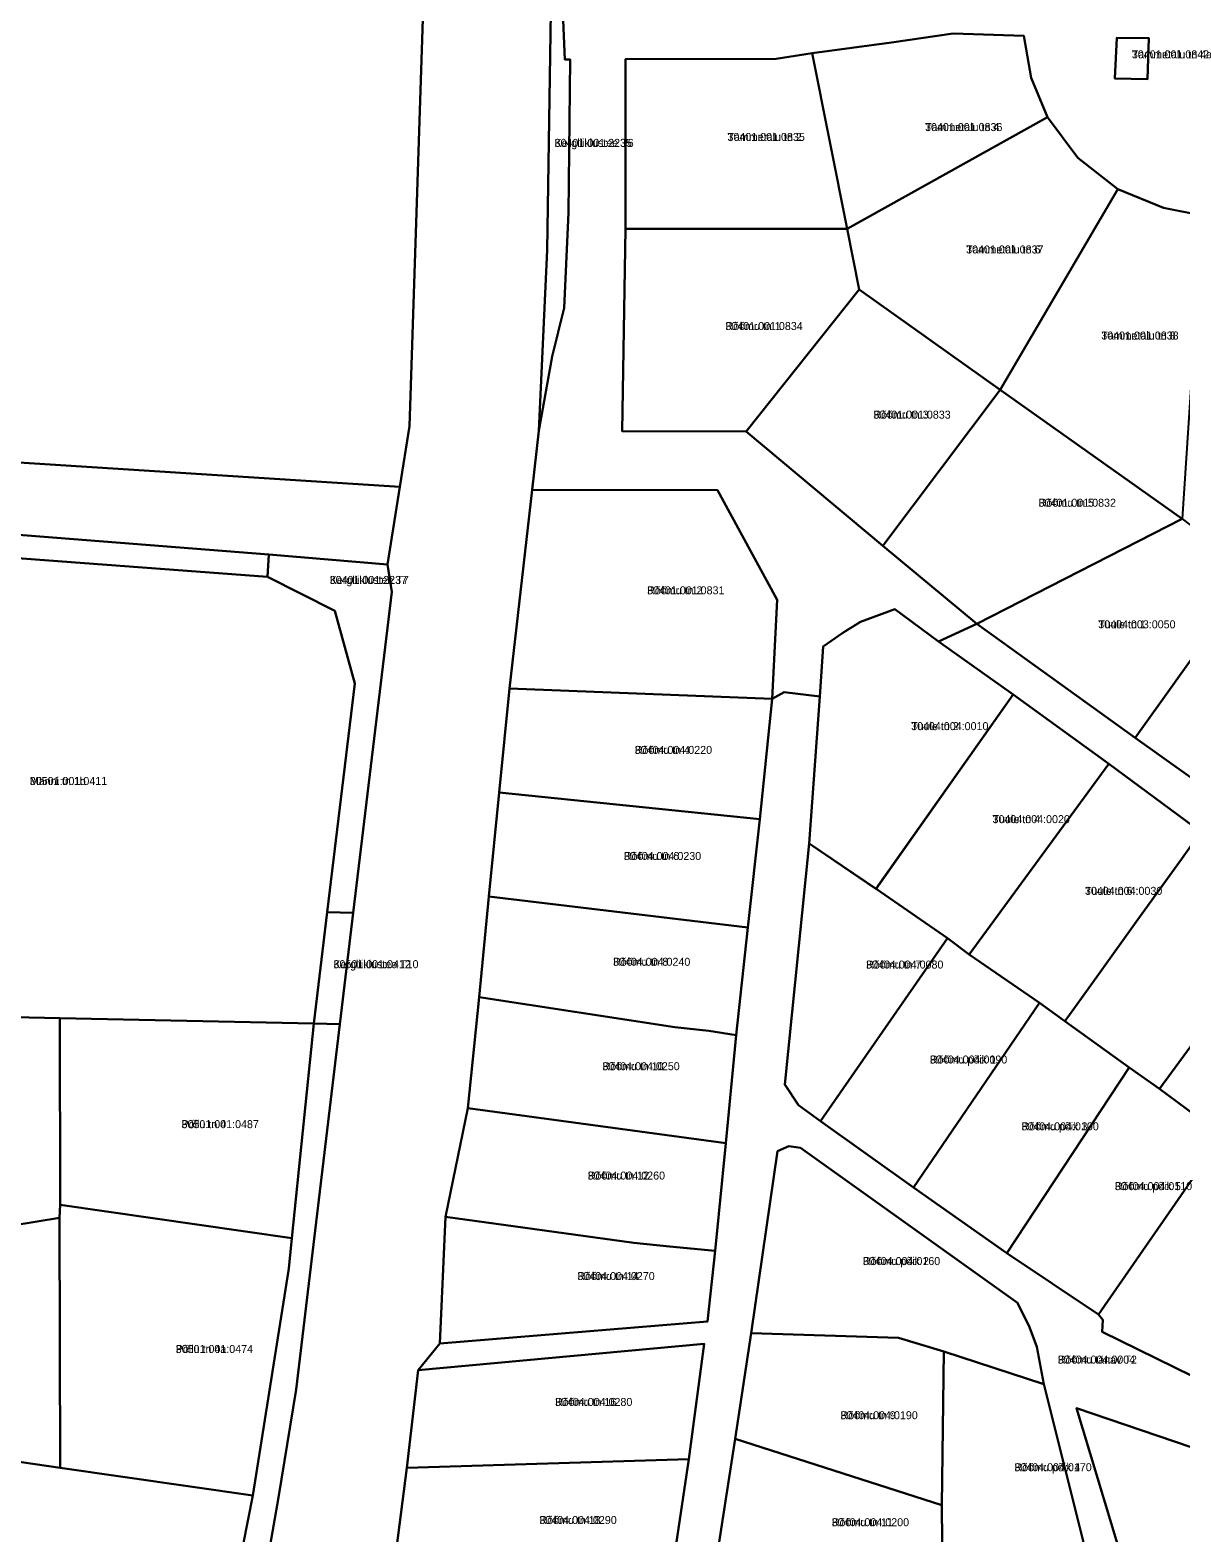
# Model space of a CAD drawing. Extents: x 542681 to 554572, y 6566489 to 6580482.
# Drawn here: x 543956.1 to 544171.9, y 6577252.9 to 6577534.7 of the extents above; entities that cross this region are included whole.
import ezdxf

# ---------------------------------------------------------------- set-up
doc = ezdxf.new("R2010")
doc.units = 0
for name, color, linetype in [('L_AADRESS', 7, 'Continuous'), ('PIIR', 7, 'Continuous'), ('TUNNUS', 7, 'Continuous')]:
    doc.layers.add(name, color=color, linetype=linetype)

msp = doc.modelspace()

# ---------------------------------------------------------------- linework, layer by layer
at = {"layer": 'PIIR'}
for points in [[(544030.15, 6577550.17), (544027.21, 6577460.39), (544025.4, 6577449.01), (543908.86, 6577456.48), (543804.25, 6577490.77), (543783.82, 6577497.46), (543778.02, 6577479.87), (543751.94, 6577490.62), (543735, 6577461.17), (543686.43, 6577482.79), (543669.69, 6577490.19), (543653.77, 6577500.52), (543645.51, 6577505.96), (543637.34, 6577511.56), (543597.54, 6577553.16)], [(543807.92, 6576662.98), (543904.97, 6576885.47), (543907.57, 6576895.31), (543910.99, 6576906.44), (543922.56, 6576941.94), (543936.45, 6576984.61), (543948.61, 6577021.3), (543957.88, 6577054.74), (543966.17, 6577087.14), (543974.03, 6577119.2), (543981.47, 6577151), (543988.44, 6577183.28), (543996.05, 6577221.97), (544002.64, 6577259.57), (544005.96, 6577279.79), (544014.14, 6577348.31), (544016.62, 6577369.15), (544023.92, 6577429.37), (544023.1, 6577434.48), (544025.4, 6577449.01), (544027.21, 6577460.39), (544030.15, 6577550.17)], [(544053.92, 6577550.31), (544053, 6577493.41), (544051.47, 6577459.51), (544050.21, 6577448.48), (544045.96, 6577411.21), (544044.02, 6577391.73), (544042.07, 6577372.25), (544040.3, 6577353.35), (544038.17, 6577332.56), (544033.93, 6577312.2), (544032.9, 6577288.43), (544028.86, 6577283.44), (544026.68, 6577265.1), (544024.78, 6577250.04)], [(544175.84, 6577499.89), (544168.56, 6577501.31), (544160.05, 6577504.83), (544152.54, 6577510.7), (544146.85, 6577518.33), (544143.77, 6577525.72), (544142.4, 6577533.6), (544129.14, 6577534.02), (544117.57, 6577532.36), (544102.69, 6577530.34), (544095.98, 6577529.27), (544067.7, 6577529.24), (544067.69, 6577497.41), (544067.11, 6577459.44), (544090.36, 6577459.43), (544115.96, 6577438), (544133.57, 6577423.36), (544126.41, 6577420.01), (544118.24, 6577426.07), (544111.75, 6577423.71), (544108.45, 6577421.66), (544104.77, 6577419.12), (544104.17, 6577409.74), (544097.43, 6577410.56), (544095.19, 6577409.28), (544096.12, 6577427.83), (544084.94, 6577448.42), (544050.21, 6577448.48), (544051.47, 6577459.51), (544053.95, 6577473.5), (544056.21, 6577482.62), (544057.04, 6577500.43), (544057.35, 6577529.17), (544056.35, 6577529.16), (544055.44, 6577549.92)], [(543908.86, 6577456.48), (544025.4, 6577449.01), (544023.1, 6577434.48), (544000.84, 6577436.33), (543906.97, 6577443.7)], [(544075.94, 6577242.44), (544079.61, 6577266.72), (544082.45, 6577288.34), (544028.86, 6577283.44), (544032.9, 6577288.43), (544083.08, 6577292.53), (544084.54, 6577305.77), (544086.52, 6577325.97), (544088.49, 6577346.24), (544090.62, 6577366.41), (544092.91, 6577386.7), (544095.19, 6577409.28), (544097.43, 6577410.56), (544104.17, 6577409.74), (544102.13, 6577382.17), (544097.57, 6577336.98), (544100.14, 6577333.11), (544104.25, 6577330.14), (544121.74, 6577317.66), (544139.24, 6577305.35), (544156.41, 6577293.87), (544157.23, 6577292.89), (544157.1, 6577290.6), (544174, 6577282.28)], [(543952.91, 6577055.9), (543961.04, 6577087.76), (543969.28, 6577119.84), (543973.68, 6577136.98), (543976.6, 6577151.88), (543983, 6577184.45), (543990.52, 6577222.87), (543997.84, 6577259.95), (544004.56, 6577302.46), (544005.14, 6577308.18), (544009.28, 6577348.44), (544014.14, 6577348.31), (544005.96, 6577279.79), (544002.64, 6577259.57), (543996.05, 6577221.97), (543988.44, 6577183.28), (543981.47, 6577151), (543974.03, 6577119.2), (543966.17, 6577087.14), (543957.88, 6577054.74), (543948.61, 6577021.3)], [(544154.25, 6577248.45), (544146.15, 6577280.82), (544144.86, 6577287.82), (544143.45, 6577291.51), (544141.23, 6577296.05), (544100.5, 6577325.14), (544098.33, 6577325.44), (544096.24, 6577324.51), (544091.27, 6577290.34), (544088.25, 6577270.53), (544083.69, 6577241.1)], [(544202.58, 6577252.78), (544201.13, 6577259.66), (544152.26, 6577276.33), (544162.33, 6577242.91)]]:
    msp.add_lwpolyline(points, dxfattribs=at)
for points in [[(544053.92, 6577550.31), (544055.44, 6577549.92), (544056.35, 6577529.16), (544057.35, 6577529.17), (544057.04, 6577500.43), (544056.21, 6577482.62), (544053.95, 6577473.5), (544051.47, 6577459.51), (544053, 6577493.41)], [(544102.69, 6577530.34), (544117.57, 6577532.36), (544129.14, 6577534.02), (544142.4, 6577533.6), (544143.77, 6577525.72), (544146.85, 6577518.33), (544109.25, 6577497.43)], [(544159.85, 6577533.24), (544165.86, 6577533.15), (544165.61, 6577525.48), (544159.44, 6577525.56)], [(544165.86, 6577533.15), (544159.85, 6577533.24), (544159.44, 6577525.56), (544165.61, 6577525.48)], [(544067.7, 6577529.24), (544095.98, 6577529.27), (544102.69, 6577530.34), (544109.25, 6577497.43), (544067.69, 6577497.41)], [(544109.25, 6577497.43), (544146.85, 6577518.33), (544152.54, 6577510.7), (544160.05, 6577504.83), (544137.99, 6577467.25), (544111.52, 6577486.02)], [(544160.05, 6577504.83), (544168.56, 6577501.31), (544175.84, 6577499.89), (544172.06, 6577443.05), (544137.99, 6577467.25)], [(544067.69, 6577497.41), (544109.25, 6577497.43), (544111.52, 6577486.02), (544090.36, 6577459.43), (544067.11, 6577459.44)], [(544111.52, 6577486.02), (544137.99, 6577467.25), (544115.96, 6577438), (544090.36, 6577459.43)], [(544137.99, 6577467.25), (544172.06, 6577443.05), (544133.57, 6577423.36), (544115.96, 6577438)], [(544050.21, 6577448.48), (544084.94, 6577448.42), (544096.12, 6577427.83), (544095.19, 6577409.28), (544045.96, 6577411.21)], [(543879.74, 6577351.15), (543904.27, 6577442.25), (543906.97, 6577443.7), (544000.84, 6577436.33), (544000.56, 6577432.17), (543924.39, 6577437.83), (543912.68, 6577434.71), (543905.78, 6577424.71), (543886.12, 6577351), (543885.8, 6577343.62), (543892.78, 6577300.8), (543888.2, 6577300.08)], [(544163.25, 6577401.97), (544133.57, 6577423.36), (544172.06, 6577443.05), (544185.38, 6577432.88)], [(543905.78, 6577424.71), (543912.68, 6577434.71), (543924.39, 6577437.83), (544000.56, 6577432.17), (544013.18, 6577425.8), (544016.98, 6577412.17), (544011.76, 6577369.27), (544009.28, 6577348.44), (543961.61, 6577349.42), (543921.15, 6577350.31), (543886.12, 6577351)], [(544000.84, 6577436.33), (544023.1, 6577434.48), (544023.92, 6577429.37), (544016.62, 6577369.15), (544011.76, 6577369.27), (544016.98, 6577412.17), (544013.18, 6577425.8), (544000.56, 6577432.17)], [(544163.25, 6577401.97), (544185.38, 6577432.88), (544196.38, 6577424.9), (544206.32, 6577417.64), (544184.57, 6577386.76)], [(544104.17, 6577409.74), (544104.77, 6577419.12), (544108.45, 6577421.66), (544111.75, 6577423.71), (544118.24, 6577426.07), (544126.41, 6577420.01), (544140.38, 6577410.12), (544114.67, 6577373.68), (544102.13, 6577382.17)], [(544133.57, 6577423.36), (544163.25, 6577401.97), (544184.57, 6577386.76), (544205.61, 6577371.6), (544227.39, 6577355.94), (544248.54, 6577340.99), (544254.71, 6577336.16), (544251.67, 6577330.24), (544251.2, 6577329.49), (544246.47, 6577333.34), (544229.05, 6577346.22), (544210.56, 6577358.48), (544193.75, 6577371.48), (544175.61, 6577384.37), (544158.34, 6577397.13), (544140.43, 6577410.12), (544126.41, 6577420.01)], [(544045.96, 6577411.21), (544095.19, 6577409.28), (544092.91, 6577386.7), (544044.02, 6577391.73)], [(544128.08, 6577364.43), (544114.72, 6577373.69), (544140.43, 6577410.12), (544158.34, 6577397.13), (544132.12, 6577361.35)], [(544150.11, 6577348.83), (544145.33, 6577352.28), (544132.12, 6577361.35), (544158.34, 6577397.13), (544175.61, 6577384.37), (544171.94, 6577379.25), (544163.79, 6577367.89), (544156.39, 6577357.58), (544150.65, 6577349.58)], [(544044.02, 6577391.73), (544092.91, 6577386.7), (544090.62, 6577366.41), (544042.07, 6577372.25)], [(544100.14, 6577333.11), (544097.57, 6577336.98), (544102.13, 6577382.17), (544114.72, 6577373.69), (544128.08, 6577364.43), (544104.25, 6577330.14)], [(544162.15, 6577340.2), (544150.11, 6577348.83), (544150.65, 6577349.58), (544156.39, 6577357.58), (544163.79, 6577367.89), (544171.94, 6577379.25), (544175.61, 6577384.37), (544193.75, 6577371.48), (544167.85, 6577336.16)], [(544042.07, 6577372.25), (544090.62, 6577366.41), (544088.49, 6577346.24), (544083.32, 6577347.04), (544076.95, 6577347.74), (544040.3, 6577353.35)], [(544179.67, 6577327.41), (544167.85, 6577336.16), (544193.75, 6577371.48), (544210.56, 6577358.48), (544183.44, 6577323.16)], [(544009.28, 6577348.44), (544011.76, 6577369.27), (544016.62, 6577369.15), (544014.14, 6577348.31)], [(544104.25, 6577330.14), (544128.08, 6577364.43), (544132.12, 6577361.35), (544145.33, 6577352.28), (544121.74, 6577317.66)], [(544040.3, 6577353.35), (544076.95, 6577347.74), (544083.32, 6577347.04), (544088.49, 6577346.24), (544086.52, 6577325.97), (544038.17, 6577332.56)], [(544121.74, 6577317.66), (544145.33, 6577352.28), (544150.11, 6577348.83), (544162.15, 6577340.2), (544139.24, 6577305.35)], [(543928.36, 6577306.55), (543921.15, 6577350.31), (543961.61, 6577349.42), (543961.68, 6577314.4), (543961.6, 6577311.99)], [(543961.68, 6577314.4), (543961.61, 6577349.42), (544009.28, 6577348.44), (544005.14, 6577308.18)], [(544139.24, 6577305.35), (544162.15, 6577340.2), (544167.85, 6577336.16), (544179.67, 6577327.41), (544156.41, 6577293.87)], [(544038.17, 6577332.56), (544086.52, 6577325.97), (544084.54, 6577305.77), (544075.93, 6577306.62), (544069.3, 6577307.33), (544033.93, 6577312.2)], [(544096.24, 6577324.51), (544098.33, 6577325.44), (544100.5, 6577325.14), (544141.23, 6577296.05), (544143.45, 6577291.51), (544144.86, 6577287.82), (544146.15, 6577280.82), (544127.37, 6577286.93), (544118.92, 6577289.5), (544091.27, 6577290.34)], [(544157.1, 6577290.6), (544157.23, 6577292.89), (544156.41, 6577293.87), (544179.67, 6577327.41), (544183.44, 6577323.16), (544196.46, 6577315.15), (544174, 6577282.28)], [(543961.6, 6577311.99), (543961.68, 6577314.4), (544005.14, 6577308.18), (544004.56, 6577302.46), (543997.84, 6577259.95), (543961.72, 6577265.1)], [(543892.78, 6577300.8), (543928.36, 6577306.55), (543961.6, 6577311.99), (543961.72, 6577265.1), (543905.31, 6577273.35), (543898.1, 6577274.48), (543888.2, 6577300.08)], [(544033.93, 6577312.2), (544069.3, 6577307.33), (544075.93, 6577306.62), (544084.54, 6577305.77), (544083.08, 6577292.53), (544032.9, 6577288.43)], [(544091.27, 6577290.34), (544118.92, 6577289.5), (544127.37, 6577286.93), (544127.01, 6577258.11), (544088.25, 6577270.53)], [(544028.86, 6577283.44), (544082.45, 6577288.34), (544079.61, 6577266.72), (544026.68, 6577265.1)], [(544127.01, 6577258.11), (544127.37, 6577286.93), (544146.15, 6577280.82), (544154.25, 6577248.45), (544127.12, 6577244.26)], [(544152.26, 6577276.33), (544201.13, 6577259.66), (544202.58, 6577252.78), (544190.01, 6577252.52), (544162.33, 6577242.91)], [(543915.25, 6577241.33), (543905.31, 6577273.35), (543961.72, 6577265.1), (543997.84, 6577259.95), (543990.52, 6577222.87), (543951.6, 6577232.38), (543945.76, 6577233.79)], [(544088.25, 6577270.53), (544127.01, 6577258.11), (544127.12, 6577244.26), (544127.14, 6577237.81), (544083.69, 6577241.1)], [(544026.68, 6577265.1), (544079.61, 6577266.72), (544075.94, 6577242.44), (544024.78, 6577250.04)]]:
    msp.add_lwpolyline(points, close=True, dxfattribs=at)

# ---------------------------------------------------------------- texts
at = {"layer": 'L_AADRESS'}
for s, p in [('Tammetalu tn 4a', (544162.65, 6577529.36)), ('Tammetalu tn 4', (544123.88, 6577515.73)), ('Kergliiklustee T6', (544054.41, 6577512.77)), ('Tammetalu tn 2', (544086.83, 6577513.88)), ('Tammetalu tn 6', (544131.58, 6577492.79)), ('Rõõmu tn 1', (544086.44, 6577478.43)), ('Tammetalu tn 8', (544156.92, 6577476.65)), ('Rõõmu tn 3', (544114.18, 6577461.82)), ('Rõõmu tn 5', (544145.17, 6577445.3)), ('Kergliiklustee T7', (544012.24, 6577430.83)), ('Rõõmu tn 2', (544071.76, 6577428.88)), ('Tuule tn 1', (544156.35, 6577422.51)), ('Tuule tn 2', (544121.26, 6577403.42)), ('Rõõmu tn 4', (544069.44, 6577398.96)), ('Männi tn 1b', (543956.01, 6577393.13)), ('Tuule tn 4', (544136.53, 6577385.98)), ('Rõõmu tn 6', (544067.4, 6577379.07)), ('Tuule tn 6', (544153.86, 6577372.54)), ('Kergliiklustee T10', (544012.95, 6577358.79)), ('Rõõmu tn 8', (544065.36, 6577359.24)), ('Rõõmu tn 7', (544112.82, 6577358.72)), ('Rõõmu põik 1', (544124.79, 6577340.92)), ('Rõõmu tn 10', (544063.37, 6577339.66)), ('Põllu tn 4', (543984.46, 6577328.8)), ('Rõõmu põik 3', (544141.95, 6577328.39)), ('Rõõmu tn 12', (544060.62, 6577319.16)), ('Rõõmu põik 5', (544159.46, 6577317.18)), ('Rõõmu põik 2', (544112.22, 6577303.13)), ('Rõõmu tn 14', (544058.68, 6577300.32)), ('Põllu tn 4a', (543983.37, 6577286.65)), ('Rõõmu tänav T2', (544148.77, 6577284.66)), ('Rõõmu tn 16', (544054.49, 6577276.72)), ('Rõõmu tn 9', (544108.01, 6577274.23)), ('Rõõmu põik 4', (544140.63, 6577264.48)), ('Rõõmu tn 18', (544051.56, 6577254.58)), ('Rõõmu tn 11', (544106.38, 6577254.17))]:
    msp.add_text(s, height=1.5, dxfattribs=at).set_placement(p)
at = {"layer": 'TUNNUS'}
for s, p in [('30401:001:0842', (544162.65, 6577529.36)), ('30401:001:0836', (544123.88, 6577515.73)), ('30401:001:2235', (544054.41, 6577512.77)), ('30401:001:0835', (544086.83, 6577513.88)), ('30401:001:0837', (544131.58, 6577492.79)), ('30401:001:0834', (544086.44, 6577478.43)), ('30401:001:0838', (544156.92, 6577476.65)), ('30401:001:0833', (544114.18, 6577461.82)), ('30401:001:0832', (544145.17, 6577445.3)), ('30401:001:2237', (544012.24, 6577430.83)), ('30401:001:0831', (544071.76, 6577428.88)), ('30404:003:0050', (544156.35, 6577422.51)), ('30404:004:0010', (544121.26, 6577403.42)), ('30404:004:0220', (544069.44, 6577398.96)), ('30501:001:0411', (543956.01, 6577393.13)), ('30404:004:0020', (544136.53, 6577385.98)), ('30404:004:0230', (544067.4, 6577379.07)), ('30404:004:0030', (544153.86, 6577372.54)), ('30501:001:0412', (544012.95, 6577358.79)), ('30404:004:0240', (544065.36, 6577359.24)), ('30404:004:0080', (544112.82, 6577358.72)), ('30404:004:0090', (544124.79, 6577340.92)), ('30404:004:0250', (544063.37, 6577339.66)), ('30501:001:0487', (543984.46, 6577328.8)), ('30404:004:0100', (544141.95, 6577328.39)), ('30404:004:0260', (544060.62, 6577319.16)), ('30404:004:0110', (544159.46, 6577317.18)), ('30404:004:0160', (544112.22, 6577303.13)), ('30404:004:0270', (544058.68, 6577300.32)), ('30501:001:0474', (543983.37, 6577286.65)), ('30404:004:0004', (544148.77, 6577284.66)), ('30404:004:0280', (544054.49, 6577276.72)), ('30404:004:0190', (544108.01, 6577274.23)), ('30404:004:0170', (544140.63, 6577264.48)), ('30404:004:0290', (544051.56, 6577254.58)), ('30404:004:0200', (544106.38, 6577254.17))]:
    msp.add_text(s, height=1.5, dxfattribs=at).set_placement(p)

doc.saveas('drawing.dxf')
